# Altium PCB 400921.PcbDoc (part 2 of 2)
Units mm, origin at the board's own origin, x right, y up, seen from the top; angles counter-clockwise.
Board outline 33 x 32.99 mm, 4 copper layers (Top Layer, Mid-Layer 1, Mid-Layer 2, Bottom Layer), stack 0.75 mm thick; 113 components, 68 nets, 329 pads, 369 vias.
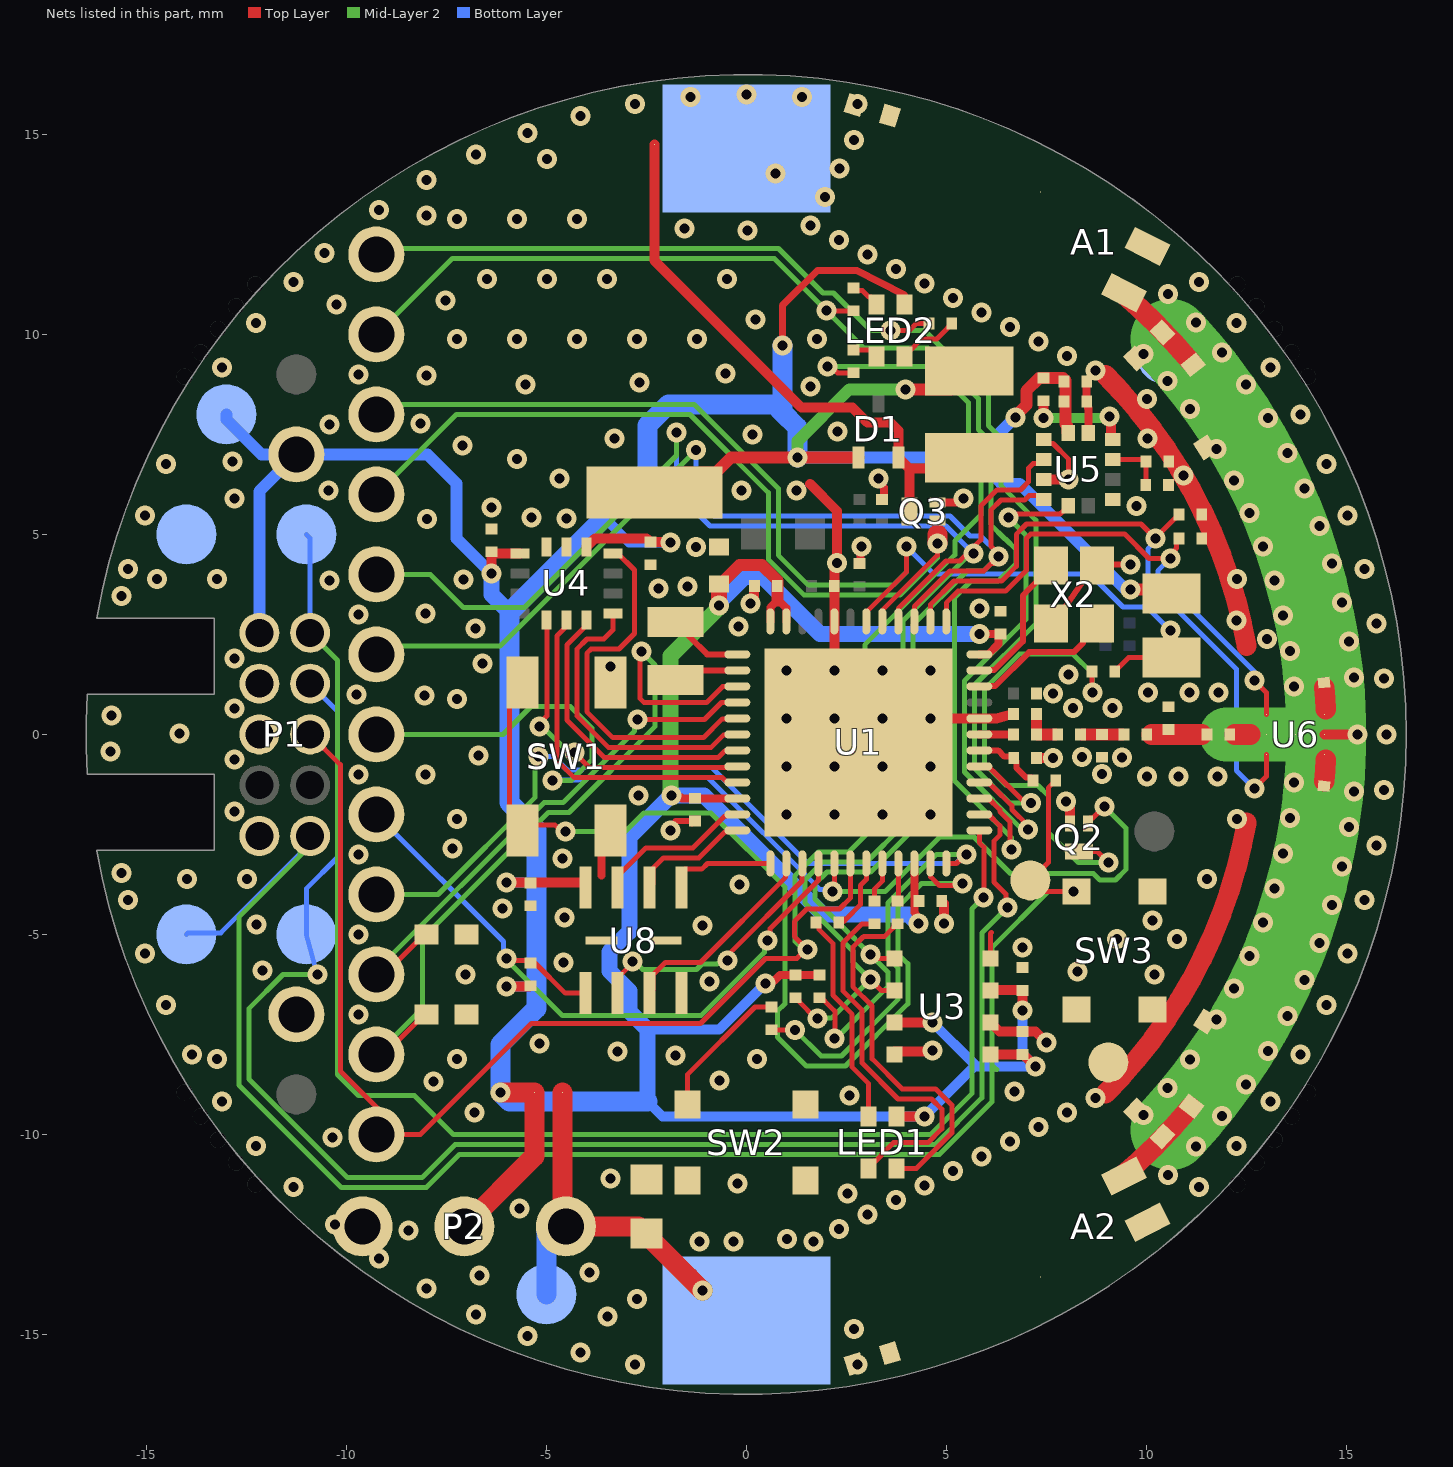
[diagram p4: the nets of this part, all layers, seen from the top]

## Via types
v1: diameter 0.5, hole 0.25, Top Layer to Bottom Layer, tented both sides, 369 vias

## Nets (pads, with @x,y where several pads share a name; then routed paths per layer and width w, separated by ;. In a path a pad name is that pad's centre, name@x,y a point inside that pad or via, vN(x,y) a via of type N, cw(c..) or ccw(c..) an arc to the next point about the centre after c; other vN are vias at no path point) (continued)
GND: A1.2 A2.2 Bat1.2 C1.1 C2.1 C3.1 C4.2 C5.1 C6.1 C7.2 C8.2 C9.1 C10.2 C11.1 C12.1 C13.1 C15.1 C16.1 C17.2 C18.1 C19.2 C20.1 C21.1 C22.1 C23.1 C24.1 C26.1 C27.1 C30.1 C31.1 C38.2 C39.1 C41.1 C42.1 GND.1 P1.3 P1.5 P1.9 P2.3 Q2.2 Q3.2 R8.1 R9.1 SW1.1 SW2.2 SW3.1 TP2.1 TP7.1 TP13.1 U1.32 U1.44 U1.49 U3.1 U3.5 U3.7 U4.6 U4.7 U5.1 U5.3 U5.7 U5.11 U6.5 U6.7 U8.4 U8.9 X2.2 X2.4 | length 63
  Top Layer w0.125: U3.5@6.1,-5.6 6.1,-4.975 6.125,-4.95 ; U5.1@7.44,7.375 7.542,7.273 7.668,7.273 8.05,6.89 v1(8.05,6.375)
  Top Layer w0.15: v1@-1.85,-2.25 -1.766,-2.166 C7.2@-1.287,-2.166 -1.302,-2.166 C7.2@-1.362,-2.226 ; X2.4@7.612,2.779 7.962,3.179 8.412,3.829 X2.2@8.762,4.229 ; X2.2@8.762,4.204 8.808,4.25 v1(9.6,4.25)
  Top Layer w0.2: -3.625,-3.525 -3.625,-2.625 SW1.1@-3.4,-2.4 ; C12.1@2.828,4.272 2.853,4.297 2.853,4.673 v1(2.879,4.698) ; v1(3.3,6.4) 3.3,6.319 3.44,6.179 C2.1@3.44,5.907 ; Q3.2@4.775,5.8 v1@5.425,5.8 ; C22.1@8.51,8.825 C21.1@8.51,8.325 8.545,8.29 8.545,8.163 8.55,8.158 U5.11@8.55,7.535 8.55,8.135
  Top Layer w0.25: v1(0.11,3.276) 0.11,3.343 0.196,3.429 0.196,3.697 C10.2@0.206,3.707 ; 1.59,6.265 2.269,5.587 2.269,4.224 2.21,4.165 2.21,3.719 C1.1@2.2,3.709 U1.44@2.2,2.825 v1(2.2,1.6) ; U3.1@3.7,-7.925 v1@4.65,-7.925 ; U1.49@4.603,0.4 U1.32@5.825,0.4 6.254,0.4 C6.1@6.681,0.514 ; C8.2@4.889,-4.162 4.889,-4.177 4.937,-4.225 v1(4.937,-4.725) ; U3.7@6.1,-7.2 6.33,-7.43 C16.1@6.9,-7.43 7.23,-7.43 v1(7.5,-7.7) ; C13.1@7.258,-0.586 v1@7.661,-0.586 ; U5.3@7.44,6.375 v1(8.05,6.375) ; Q2.2@8.087,-2.225 v1@8.087,-1.739 ; U6.5@14.45,0 v1(15.275,0)
  Top Layer w0.5: 8.98,-8.98 ccw(c0,0) 12.507,-2.205 ; 8.98,8.98 cw(c0,0) 12.507,2.205
  Mid-Layer 2 w1.35: 12.001,0 14.5,0
  Mid-Layer 2 w2: 10.605,-9.889 ccw(c0,0) 10.605,9.889
  other v1: -2.778,-15.757 2.778,-15.757 -4.141,-15.455 -5.472,-15.035 2.689,-14.863 -3.475,-14.55 -6.762,-14.501 -2.732,-14.118 -8,-13.856 -6.675,-13.525 -3.925,-13.45 -9.177,-13.106 -1.175,-12.675 -0.325,-12.675 1.675,-12.675 1.018,-12.618 -8.45,-12.4 2.313,-12.362 -10.285,-12.257 3.026,-11.999 -5.675,-11.85 3.738,-11.635 2.525,-11.475 -11.314,-11.314 11.314,-11.314 4.451,-11.272 -0.225,-11.225 -3.4,-11.1 10.546,-11.016 5.164,-10.909 5.877,-10.546 11.243,-10.303 -12.257,-10.285 12.257,-10.285 6.59,-10.183 -10.35,-10.075 7.303,-9.82 11.893,-9.545 9.932,-9.508 -6.8,-9.45 8.015,-9.456 -13.106,-9.177 13.106,-9.177 8.728,-9.093 2.575,-9.025 6.7,-8.925 10.533,-8.838 12.492,-8.747 -7.825,-8.675 -0.675,-8.65 11.089,-8.13 -13.232,-8.118 -7.232,-8.118 0.268,-8.118 -1.775,-8.025 -13.856,-8 13.856,-8 -3.225,-7.925 4.65,-7.9 13.037,-7.911 -5.175,-7.725 11.755,-7.133 13.527,-7.042 -9.7,-7 -14.501,-6.762 14.501,-6.762 12.196,-6.349 -0.925,-6.175 13.958,-6.142 -7.025,-6 10.2,-6 8.275,-5.925 -12.1,-5.9 -4.575,-5.7 12.586,-5.538 -15.035,-5.472 15.035,-5.472 6.9,-5.325 14.33,-5.216 9.268,-5.118 10.768,-5.118 -9.7,-5 -1.1,-4.775 -12.25,-4.75 12.921,-4.703 10.15,-4.65 -4.55,-4.575 -6.1,-4.35 14.641,-4.267 -15.455,-4.141 15.455,-4.141 13.201,-3.848 -0.175,-3.75 -13.982,-3.618 -12.482,-3.618 11.518,-3.618 -15.621,-3.463 14.888,-3.301 -4.6,-3.1 -9.7,-3 13.424,-2.976 -7.35,-2.85 15.757,-2.778 -1.9,-2.4 15.072,-2.32 -7.232,-2.118 12.268,-2.118 13.59,-2.092 1,-2 2.2,-2 3.4,-2 4.6,-2 -12.8,-1.925 7.988,-1.676 -2.7,-1.525 15.192,-1.429 15.939,-1.394 13.698,-1.198 10.016,-1.05 10.803,-1.05 11.775,-1.05 -9.7,-1 -8.025,-1 8.898,-0.989 1,-0.8 2.2,-0.8 3.4,-0.8 4.6,-0.8 -12.8,-0.625 7.666,-0.591 8.391,-0.56 9.394,-0.571 -6.7,-0.525 -15.9,-0.425 16,0 -14.175,0.025 1,0.4 2.2,0.4 3.4,0.4 4.6,0.4 -15.875,0.475 -12.8,0.65 8.162,0.659 9.152,0.659 -7.232,0.882 -8.05,0.975 -9.75,1 7.666,1.02 10.041,1.05 11.075,1.05 11.8,1.05 13.698,1.198 15.939,1.394 15.192,1.429 8.06,1.498 1,1.6 3.4,1.6 4.6,1.6 -3.4,1.7 -6.6,1.775 -12.8,1.9 13.59,2.092 15.072,2.32 13.018,2.382 -6.775,2.65 -0.2,2.702 15.757,2.778 12.25,2.85 13.424,2.976 -9.7,3 -8.025,3.025 5.825,3.149 14.888,3.301 -15.621,3.463 -2.2,3.65 -1.475,3.7 -10.425,3.85 13.201,3.848 -14.732,3.882 -13.232,3.882 -7.075,3.875 12.268,3.882 -15.455,4.141 15.455,4.141 14.641,4.267 2.269,4.292 -1.263,4.685 12.921,4.703 14.33,5.216 -7.982,5.382 -4.5,5.4 -5.375,5.425 -15.035,5.472 15.035,5.472 12.586,5.538 -6.375,5.675 9.75,5.707 -12.8,5.9 5.425,5.9 -10.45,6.1 -0.125,6.1 1.25,6.1 13.958,6.142 12.196,6.349 -4.675,6.4 10.926,6.474 -14.501,6.762 14.501,6.762 -12.85,6.825 -5.732,6.882 13.527,7.042 11.755,7.133 -7.1,7.225 -3.3,7.4 10.025,7.4 0.15,7.5 2.275,7.575 -10.425,7.75 -8.15,7.775 13.037,7.911 13.856,8 11.089,8.13 10.018,8.382 1.6,8.7 -5.525,8.75 12.492,8.747 -2.675,8.8 10.533,8.838 -8,8.975 -9.7,9 -0.525,9.025 8.728,9.093 -13.106,9.177 -13.106,9.177 13.106,9.177 8.015,9.456 9.932,9.508 11.893,9.545 7.303,9.82 -7.232,9.882 -5.732,9.882 -4.232,9.882 -2.732,9.882 -1.232,9.882 1.768,9.882 6.59,10.183 -12.257,10.285 -12.257,10.285 12.257,10.285 11.243,10.303 0.225,10.375 5.877,10.546 -10.25,10.75 -7.525,10.85 5.164,10.909 10.546,11.016 4.451,11.272 -11.314,11.314 11.314,11.314 -6.482,11.382 -4.982,11.382 -3.482,11.382 -0.482,11.382 3.738,11.635 3.026,11.999 -10.55,12.029 2.313,12.362 0.025,12.6 -1.55,12.65 1.6,12.725 -7.232,12.882 -5.732,12.882 -4.232,12.882 -8,12.975 -9.177,13.106 1.963,13.438 -8,13.856 0.725,14.025 2.326,14.151 -4.982,14.382 -6.762,14.501 2.69,14.863 -5.472,15.035 -4.141,15.455 -2.778,15.757 2.778,15.757 -1.394,15.939 1.394,15.939 0,16
J1: C29.2 U6.6 | length 0.5
  Top Layer w0.517: C29.2@14.453,1.171 cw(c0,0) 14.486,0.634
J2: C25.2 U6.4 | length 0.5
  Top Layer w0.517: C25.2@14.453,-1.171 ccw(c0,0) 14.486,-0.634
NetA1_1: A1.1 C31.2 L7.2 | length 2.5
  Top Layer w0.517: A1.1@9.34,11.091 cw(c0,0) L7.2@11.102,9.327
NetA1_3: A1.3 C42.2
NetA2_1: A2.1 C27.2 C40.2 | length 2.5
  Top Layer w0.517: A2.1@9.34,-11.091 ccw(c0,0) C40.2@11.102,-9.327
NetA2_3: A2.3 C41.2
NetBz1_2: Bz1.2 D1.2 L6.1 Q3.3 | length 14.5
  Top Layer w0.25: Bz1.2@-2.3,14.75 -2.3,11.85 1.375,8.175 2.65,8.175 3.025,7.8 3.6,7.8 3.8,7.6 D1.2@3.8,6.925 4.075,6.65 ; Q3.3@4.075,5.575 4.075,6.65 ; L6.1@5.575,6.915 5.31,6.65 4.075,6.65
NetC6_2: C6.2 L2.2 L3.1 | length 0.9
  Top Layer w0.27: L2.2@7.253,0.014 C6.2@7.253,0.507
  Top Layer w0.3: L2.2@7.28,-0.001 L3.1@7.73,-0.001
NetC9_2: C9.2 L3.2 L4.1 | length 1
  Top Layer w0.3: L3.2@8.391,-0.001 C9.2@8.898,-0.001 L4.1@9.406,-0.001
NetC13_2: C13.2 R1.1 U1.30 | length 1.7
  Top Layer w0.15: U1.30@5.825,-0.4 6.297,-0.4 6.452,-0.555 6.635,-0.555 C13.2@6.685,-0.605 ; C13.2@6.684,-0.613 6.7,-0.613 6.755,-0.669 6.755,-0.74 6.757,-0.742 6.757,-0.843 6.996,-1.082 R1.1@7.136,-1.082
NetL2_1: L2.1 U1.31 | length 0.9
  Top Layer w0.2: U1.31@5.825,0 6.682,0 L2.1@6.683,-0.001
NetLED1_1: LED1.1 R13.2 | length 5.4
  Top Layer w0.125: R13.2@1.74,-4.7 1.812,-4.772 1.812,-4.871 2.162,-5.221 2.162,-6.513 2.646,-6.997 2.646,-8.318 3.05,-8.722 LED1.1@3.05,-9.55
NetLED1_2: LED1.2 R12.2 | length 9.3
  Top Layer w0.125: LED1.2@3.75,-10.85 4.25,-10.85 5.138,-9.962 5.138,-9.265 4.735,-8.862 3.897,-8.862 3.146,-8.111 3.146,-6.79 2.662,-6.306 2.662,-5.944 2.662,-5.319 2.919,-5.062 2.935,-5.062 2.94,-5.058 3.453,-5.058 3.688,-4.822 3.688,-4.807 3.76,-4.735 R12.2@3.775,-4.735
NetLED1_3: LED1.3 R11.2 | length 9.4
  Top Layer w0.125: LED1.3@3.05,-10.85 3.05,-10.8 3.187,-10.662 3.238,-10.662 3.362,-10.538 3.362,-10.522 3.685,-10.2 4.546,-10.2 4.887,-9.859 4.887,-9.369 4.631,-9.113 3.794,-9.113 2.896,-8.215 2.896,-6.893 2.412,-6.41 2.412,-5.215 2.893,-4.735 R11.2@3.2,-4.735
NetLED2_1: LED2.1 R16.2 | length 0.8
  Top Layer w0.125: R16.2@2.675,11.16 2.743,11.092 2.908,11.092 3.063,10.937 3.113,10.937 3.25,10.8 LED2.1@3.25,10.75
NetLED2_2: LED2.2 R15.2 | length 1.8
  Top Layer w0.125: LED2.2@3.95,9.45 3.95,9.5 4.088,9.637 4.138,9.637 4.215,9.715 ; 4.215,9.715 4.387,9.888 4.68,9.888 ; 4.748,9.888 4.68,9.888 ; R15.2@5.048,10.188 5.063,10.188 R15.2@5.135,10.26 ; R15.2@5.135,10.275 R15.2@5.135,10.26 ; 4.68,9.888 4.763,9.888 R15.2@5.135,10.26
NetLED2_3: LED2.3 R14.2 | length 0.8
  Top Layer w0.125: R14.2@2.675,9.61 3.113,9.61 3.25,9.473 LED2.3@3.25,9.45 LED2.3@3.365,9.335
NetQ2_3: Q2.3 R4.1 | length 11.6
  Top Layer w0.125: Q2.3@8.3,-2.925 8.775,-2.925 v1(9.05,-3.2) ; R4.1@8.64,1.575 8.64,1.06 v1(8.65,1.05)
  Mid-Layer 2 w0.125: v1(8.65,1.05) 8.65,1.527 8.165,2.011 6.836,2.011 5.957,1.132 5.957,-0.734 6.5,-1.277 7.294,-1.277 7.55,-1.533 7.55,-2.45 8.3,-3.2 v1(9.05,-3.2)
NetR5_2: R5.2 U5.10 | length 2.7
  Top Layer w0.25: v1(7.425,7.915) R5.2@7.425,8.34 ; v1(9.075,7.95) 9.121,7.904 9.121,7.414 U5.10@9.16,7.375
  Mid-Layer 2 w0.25: v1(7.425,7.915) 9.04,7.915 v1(9.075,7.95)
NetR19_1: R19.1 SW2.1 | length 3.5
  Top Layer w0.125: SW2.1@-1.475,-9.25 -1.475,-8.506 0.216,-6.815 R19.1@0.625,-6.815
P0.00: SW1.2 U1.23 | length 25.3
  Top Layer w0.125: SW1.2@-5.6,1.3 -5.925,0.975 -5.925,-2.075 SW1.2@-5.6,-2.4 -5.461,-2.261 -4.786,-2.261 -4.621,-2.425 v1(-4.525,-2.425) ; U1.23@4.609,-3.234 4.609,-3.559 4.827,-3.777 5.348,-3.777 v1(5.4,-3.725)
  Mid-Layer 2 w0.125: v1(-4.525,-2.425) -3.025,-2.425 -2.562,-1.962 -0.886,-1.962 0.962,-3.811 0.962,-6.738 0.778,-6.922 0.778,-7.566 1.502,-8.291 2.482,-8.291 4.037,-6.735 4.037,-5.73 3.788,-5.48 3.788,-4.318 4.38,-3.725 v1(5.4,-3.725)
P0.01: 0.01.1 R19.2 U1.24 | length 27.6
  Top Layer w0.125: R19.2@0.625,-7.385 v1(1.216,-7.385) ; U1.24@5,-3.225 5.254,-3.225 5.479,-3 v1(5.5,-3)
  Mid-Layer 2 w0.125: 0.01.1@-9.25,-4 -7.707,-4 -5.288,-1.58 -5.288,-0.638 v1(-5.2,-0.55) ; v1(1.216,-7.385) 1.871,-8.041 2.3,-8.041 2.303,-8.038 2.381,-8.038 3.787,-6.631 3.787,-5.834 3.537,-5.584 3.537,-4.214 4.752,-3 v1(5.5,-3)
  Bottom Layer w0.125: v1(-5.2,-0.55) -4.819,-0.55 -4.481,-0.888 -4.119,-0.888 -4.062,-0.831 -0.856,-0.831 1.538,-3.225 5.239,-3.225 5.464,-3 v1(5.5,-3)
P0.02: 0.02.1 R16.1 U1.27 | length 33
  Top Layer w0.125: v1@2,10.59 R16.1@2.675,10.59 ; U1.27@5.825,-1.6 6.057,-1.6 6.337,-1.881 6.337,-1.927 6.587,-2.177 6.587,-2.838 v1(6.625,-2.875)
  Mid-Layer 2 w0.125: 0.02.1@-9.25,10 -7.35,11.9 0.7,11.9 v1(2,10.6) 2.938,9.662 4.538,9.662 5.8,8.4 5.8,7.621 6.113,7.309 6.113,5.244 6.469,4.888 6.481,4.888 6.737,4.631 6.737,4.269 6.306,3.837 5.62,3.837 5.207,3.425 5.207,-1.157 6.625,-2.575 v1(6.625,-2.875)
P0.03: U1.28 U5.5 | length 12.8
  Top Layer w0.125: U1.28@5.835,-1.21 U1.28@5.825,-1.2 6.048,-1.2 6.161,-1.312 6.169,-1.312 6.639,-1.782 6.639,-1.875 7.037,-2.274 v1(7.037,-2.381) ; v1(6.55,5.425) 6.634,5.509 7.844,5.509 7.917,5.583 7.947,5.583 8.05,5.685 U5.5@8.05,5.715
  Mid-Layer 2 w0.125: v1(6.55,5.425) 6.988,4.988 6.988,2.87 5.457,1.339 5.457,-0.941 6.897,-2.381 v1(7.037,-2.381)
P0.04: 0.04.1 R15.1 U1.29 | length 32.1
  Top Layer w0.125: v1(3.6,10.1) 4.075,10.1 4.25,10.275 R15.1@4.565,10.275 ; U1.29@5.825,-0.8 6.05,-0.8 6.162,-0.912 6.169,-0.912 6.933,-1.676 7.226,-1.676 v1@7.264,-1.714
  Mid-Layer 2 w0.125: 0.04.1@-9.25,12 -9.1,12.15 0.804,12.15 1.916,11.038 2.181,11.038 3.119,10.1 v1(3.6,10.1) 4.454,10.1 6.05,8.504 6.05,7.725 6.363,7.412 6.363,6.231 7.238,5.356 7.238,2.766 5.707,1.235 5.707,-0.837 6.584,-1.714 v1@7.287,-1.714
  other v1: 7.112,-1.714
P1.00/XL1: U1.1 X1.2 | length 2.1
  Top Layer w0.15: X1.2@-1.998,2.781 -1.749,2.781 -1.399,2.431 -1.399,2.422 -0.977,2 U1.1@-0.225,2
P1.01/XL2: U1.2 X1.1 | length 1.9
  Top Layer w0.15: X1.1@-2.024,1.281 -1.699,1.281 -1.379,1.6 U1.2@-0.225,1.6
P1.02/NFC1: 1.02.1 C17.1 U1.3 | length 18.9
  Top Layer w0.125: 1.02.1@-9.25,-8 -9.05,-8 -8.05,-7 C17.1@-8,-7 ; v1@-2.674,2.051 v1@-2.65,2.075 ; v1@-2.661,2.039 -2.661,0.903 -2.551,0.793 -0.996,0.793 -0.589,1.2 U1.3@-0.225,1.2
  Mid-Layer 2 w0.125: 1.02.1@-9.25,-8 -8.1,-6.85 -8.1,-5.1 -4.95,-1.95 -4.431,-1.95 -2.287,0.194 -2.287,0.622 -2.284,0.625 -2.284,1.734 v1(-2.625,2.075)
P1.03/NFC2: 1.03.1 C19.1 U1.4 | length 13.7
  Top Layer w0.125: 1.03.1@-9.25,-6 -9.05,-6 -8.05,-5 C19.1@-8,-5 ; v1(-2.725,0.375) -1.045,0.375 -0.62,0.8 U1.4@-0.225,0.8
  Mid-Layer 2 w0.125: 1.03.1@-9.25,-6 -9.25,-5.896 -5.054,-1.7 -4.578,-1.7 -2.797,0.081 -2.797,0.303 v1(-2.725,0.375)
P1.04: U1.5 U4.4 | length 9.4
  Top Layer w0.125: U4.4@-3.338,4.525 -3.21,4.525 -2.794,4.109 -2.794,2.525 -3.181,2.138 -3.878,2.138 -3.988,2.028 -3.988,0.57 -3.337,-0.081 -1.069,-0.081 -0.597,0.391 U1.5@-0.234,0.391
P1.05: U1.6 U4.1 | length 7.6
  Top Layer w0.125: U4.1@-3.337,3 -3.337,2.613 -3.562,2.388 -3.981,2.388 -4.238,2.131 -4.238,0.466 -3.44,-0.331 -0.887,-0.331 -0.565,-0.009 U1.6@-0.234,-0.009
P1.06: U1.7 U4.14 | length 7.4
  Top Layer w0.125: U4.14@-4,2.813 -4,2.722 -4.488,2.235 -4.488,0.363 -3.544,-0.581 -0.705,-0.581 -0.533,-0.409 U1.7@-0.234,-0.409
P1.07: U1.8 U4.12 | length 8.1
  Top Layer w0.125: v1(-5.175,0.2) -5.175,0.273 -4.988,0.461 U4.12@-4.988,2.825 ; v1(-4.3,-0.45) -3.919,-0.831 -0.256,-0.831 U1.8@-0.225,-0.8
  Mid-Layer 2 w0.125: v1(-5.175,0.2) -5.1,0.2 -4.522,-0.378 -4.372,-0.378 v1(-4.3,-0.45)
P1.08: U1.9 U4.13 | length 8.3
  Top Layer w0.125: U4.13@-4.5,2.863 -4.5,2.7 -4.738,2.462 -4.738,-0.644 -4.3,-1.081 -0.594,-1.081 -0.475,-1.2 U1.9@-0.225,-1.2
P1.09: R8.2 U1.37 U6.1 | length 13.2
  Top Layer w0.125: U1.37@5,2.825 5,3.289 5.298,3.587 6.486,3.587 7,4.1 7,4.9 7.108,5.009 9.46,5.009 10.069,4.4 v1(10.6,4.4) 10.6,4.501 10.754,4.656 10.754,4.839 R8.2@10.815,4.9 ; v1(12.7,1.35) 13,1.05 U6.1@13,0.5
  Bottom Layer w0.125: v1(10.6,4.4) 10.289,4.089 10.289,3.986 12.7,1.575 v1(12.7,1.35)
P1.10: R9.2 U1.38 U6.3 | length 16.8
  Top Layer w0.125: U1.38@4.6,2.825 4.6,3.242 5.194,3.837 6.383,3.837 6.75,4.203 6.75,5.003 7.005,5.259 9.866,5.259 v1(10.225,4.9) 10.225,4.91 10.728,5.413 10.743,5.413 10.815,5.485 R9.2@10.815,5.5 ; v1(12.7,-1.35) 13,-1.05 U6.3@13,-0.5
  Bottom Layer w0.125: v1(10.225,4.9) 10.225,4.827 10.038,4.639 10.038,3.847 12.25,1.634 12.25,-0.9 v1(12.7,-1.35)
P1.11: 1.11.1 R3.1 U1.39 U3.4 U5.4 | length 43.7
  Top Layer w0.125: R3.1@1.825,-6.585 1.898,-6.658 1.951,-6.658 2.213,-6.919 v1@2.213,-7.587 ; v1@3.1,-5.6 v1@3.301,-5.6 ; v1(3.1,-5.5) 3.201,-5.5 v1@3.301,-5.6 ; U3.4@3.7,-5.6 v1@3.301,-5.6 ; U1.39@4.2,2.825 4.2,3.196 5.091,4.087 5.939,4.087 6.128,4.275 6.2,4.275 6.2,4.376 v1@6.287,4.463 ; v1(6.3,4.45) 6.3,4.523 6.113,4.711 6.113,5.606 6.369,5.863 6.958,5.863 7.07,5.975 7.315,5.975 7.428,5.863 U5.4@7.44,5.875
  Mid-Layer 2 w0.125: 1.11.1@-9.25,2 -9.25,2.213 -6.154,2.213 v1(-1.258,7.108) ; v1(2.2,-7.6) 2.244,-7.6 3.537,-6.306 3.537,-5.937 v1(3.1,-5.5) 2.8,-5.2 2.8,-5.196 2.654,-5.05 2.65,-5.05 1.712,-4.112 1.712,-3.744 2.017,-3.44 3.11,-3.44 4.162,-2.388 4.162,2.734 5.516,4.087 5.937,4.087 v1(6.3,4.45)
  Bottom Layer w0.125: v1(-1.258,7.108) -1.258,5.912 -0.805,5.459 5.095,5.459 5.591,4.962 5.856,4.962 6.3,4.519 v1(6.3,4.45)
P1.12: 1.12.1 R2.1 U1.40 U3.3 U5.2 | length 42.7
  Top Layer w0.125: R2.1@1.225,-6.585 1.24,-6.585 1.312,-6.658 1.312,-6.673 v1@1.74,-7.1 ; v1@1.763,-7.112 v1(1.775,-7.1) ; v1(3.1,-6.125) 3.375,-6.4 U3.3@3.7,-6.4 ; U1.40@3.8,2.825 3.8,3.149 4.987,4.337 5.333,4.337 5.45,4.453 5.502,4.453 5.598,4.55 5.598,4.602 5.863,4.866 5.863,5.71 6.265,6.113 6.854,6.113 7.057,6.316 7.057,6.657 7.173,6.773 7.337,6.773 U5.2@7.44,6.875
  Mid-Layer 2 w0.125: 1.12.1@-9.25,4 -7.9,4 -7.075,3.175 -5.545,3.175 -1.746,6.974 v1(-1.746,7.546) ; v1(1.775,-7.1) 1.784,-7.091 2.134,-7.091 v1(3.1,-6.125) 2.662,-5.687 2.662,-5.416 1.462,-4.216 1.462,-3.638 1.91,-3.19 3.007,-3.19 3.912,-2.284 3.912,2.837 5.6,4.525 v1(5.675,4.525)
  Bottom Layer w0.125: v1(-1.746,7.546) -1.746,6.046 -0.909,5.209 4.991,5.209 v1(5.675,4.525)
P1.13: 1.13.1 Q3.1 U1.41 | length 21.2
  Top Layer w0.125: U1.41@3.4,2.825 3.4,3.103 4.775,4.478 v1(4.775,4.771)
  Top Layer w0.5: v1(4.775,4.771) v1@4.775,5
  Mid-Layer 2 w0.125: 1.13.1@-9.25,6 -7.25,8 -1.406,8 0.55,6.044 0.55,4.378 1.447,3.481 3.849,3.481 4.775,4.407 v1(4.775,4.771)
P1.14: 1.14.1 Q1.E R4.2 U1.42 | length 28.3
  Top Layer w0.125: U1.42@3,2.825 3,3.057 4,4.057 v1(4,4.7) ; R4.2@9.21,1.575 9.21,1.59 9.282,1.663 9.297,1.663 9.56,1.925 Q1.E@10.625,1.925
  Mid-Layer 2 w0.125: 1.14.1@-9.25,8 -9,8.25 -1.303,8.25 0.8,6.147 0.8,4.481 1.551,3.731 3.669,3.731 4,4.061 v1(4,4.7)
  Bottom Layer w0.125: v1(4,4.7) 4.687,4.013 8.594,4.013 9.419,3.188 10.012,3.188 v1(10.6,2.6)
P2.00: U1.11 U8.7 | length 4.2
  Top Layer w0.125: U8.7@-3.275,-4.054 -3.275,-3.6 -2.513,-2.838 -1.338,-2.838 -0.537,-2.037 -0.508,-2.037 -0.47,-2 U1.11@-0.225,-2
P2.01: U1.12 U8.6 | length 3
  Top Layer w0.125: U8.6@-2.425,-3.83 -2.337,-3.743 -2.337,-3.352 -2.073,-3.088 -1.188,-3.088 -0.537,-2.437 -0.508,-2.437 -0.47,-2.4 U1.12@-0.225,-2.4
P2.02: U1.13 U8.5 | length 2.7
  Top Layer w0.125: U8.5@-1.625,-3.83 -1.625,-3.457 -1.537,-3.37 -1.116,-3.37 -0.971,-3.225 U1.13@0.6,-3.225
P2.03: U1.14 U8.3 | length 5.5
  Top Layer w0.125: U8.3@-2.425,-6.47 -2.337,-6.383 -2.337,-6.008 -2.333,-6.008 -2.025,-5.7 -1.146,-5.7 0.986,-3.569 0.986,-3.239 U1.14@1,-3.225 U1.14@1,-3.508
P2.04: U1.15 U8.2 | length 6.7
  Top Layer w0.125: U8.2@-3.225,-6.47 -3.225,-6.095 -2.85,-5.72 v1(-2.85,-5.675) ; v1(-0.475,-5.65) -0.403,-5.578 -0.403,-5.46 1.394,-3.663 1.394,-3.231 U1.15@1.4,-3.225
  Mid-Layer 2 w0.125: v1(-2.85,-5.675) -2.789,-5.675 -2.589,-5.875 -1.244,-5.875 -1.106,-5.737 -0.736,-5.737 -0.72,-5.722 -0.547,-5.722 v1(-0.475,-5.65)
P2.05: 2.05.1 R17.1 U1.16 U8.1 | length 17.8
  Top Layer w0.125: v1(-6,-5.6) -5.943,-5.657 -5.458,-5.657 R17.1@-5.4,-5.715 -5.28,-5.715 -4.525,-6.47 U8.1@-4.025,-6.47 ; v1(0.525,-5.15) 0.597,-5.078 0.597,-4.853 1.8,-3.65 U1.16@1.8,-3.225
  Mid-Layer 2 w0.125: v1(-6,-5.6) -6,-5.625 -4.6,-7.025 -1.125,-7.025 0.453,-5.447 0.453,-5.222 v1(0.525,-5.15)
  Bottom Layer w0.125: 2.05.1@-9.25,-2 -6.072,-5.178 -6.072,-5.528 v1(-6,-5.6)
P2.06: 2.06.1 Q2.1 U1.17 | length 27.7
  Top Layer w0.125: v1(2.15,-3.925) 2.2,-3.875 U1.17@2.2,-3.225 ; Q2.1@8.525,-2.225 8.525,-2.15 8.588,-2.088 8.662,-2.088 v1(8.95,-1.8)
  Mid-Layer 2 w0.125: 2.06.1@-9.25,0 -6.083,0 -5.383,0.7 -4.4,0.7 -3.862,0.162 -3.862,-0.631 -4.381,-1.15 v1(-4.85,-1.15) ; v1(2.15,-3.925) 3.473,-3.925 4.836,-2.562 5.694,-2.562 6.606,-3.475 8.675,-3.475 8.838,-3.638 9.231,-3.638 9.488,-3.381 9.488,-2.338 v1(8.95,-1.8)
  Bottom Layer w0.125: v1(-4.85,-1.15) -4.838,-1.138 -4.015,-1.138 -3.959,-1.081 -0.959,-1.081 1.833,-3.873 2.098,-3.873 v1(2.15,-3.925)
P2.07: 2.07.1 P1.6 R14.1 U1.18 | length 47.7
  Top Layer w0.125: P1.6@-10.905,0 -10.15,-0.755 -10.15,-8.414 -9.25,-9.314 2.07.1@-9.25,-10 -8.15,-10 -5.375,-7.225 -1.144,-7.225 0.481,-5.6 1.264,-5.6 1.489,-5.375 v1(1.525,-5.375) 1.2,-5.05 1.2,-4.675 1.512,-4.363 2.331,-4.363 2.6,-4.094 U1.18@2.6,-3.225 ; v1(2.025,9.2) 2.126,9.2 2.286,9.04 R14.1@2.675,9.04
  Mid-Layer 2 w0.125: v1(1.525,-5.375) 1.424,-5.375 1.294,-5.246 1.286,-5.246 1.212,-5.172 1.212,-3.534 1.807,-2.94 2.56,-2.94 2.962,-2.538 2.962,2.241 5.213,4.491 5.213,4.838 5.863,5.487 5.863,7.205 5.55,7.518 5.55,8.296 4.646,9.2 v1(2.025,9.2)
P2.08: R13.1 U1.19 | length 2
  Top Layer w0.125: R13.1@2.31,-4.7 2.31,-4.685 2.382,-4.613 2.496,-4.613 ; R13.1@2.352,-4.757 2.496,-4.613 ; U1.19@3,-3.225 3,-3.625 2.85,-3.775 2.85,-4.258 2.496,-4.613
P2.09: R11.1 U1.20 | length 1
  Top Layer w0.125: R11.1@3.2,-4.165 3.2,-3.868 3.4,-3.668 U1.20@3.4,-3.225
P2.10: R12.1 U1.21 | length 0.9
  Top Layer w0.125: R12.1@3.8,-4.14 U1.21@3.8,-3.225
RESET: P1.10 R1.2 SW3.2 TP3.1 TP12.1 | length 43.4
  Top Layer w0.125: R1.2@7.736,-1.152 7.55,-1.337 7.55,-3.2 TP12.1@7.1,-3.65 7.375,-3.925 v1(8.175,-3.925)
  Mid-Layer 2 w0.125: 6.263,-8.382 6.137,-8.257 ; v1(8.175,-3.925) 7.544,-3.925 6.137,-5.331 6.137,-8.257 ; -11.163,-3.044 -10.905,-2.786 P1.10@-10.905,-2.54 -11.163,-2.798 -11.163,-3.044 ; -11.163,-3.044 -12.688,-4.569 -12.688,-8.762 -10.125,-11.325 -8,-11.325 -7.175,-10.5 4.826,-10.5 6.137,-9.188 6.137,-8.257
  Bottom Layer w0.125: TP3.1@-14,-5 -13.961,-4.961 -13.136,-4.961 P1.10@-10.905,-2.73 ; P1.10@-10.905,-2.73 P1.10@-10.905,-2.54 P1.10@-10.905,-2.73
RF: C11.2 C28.2 L4.2 | length 1.3
  Top Layer w0.517: L4.2@10.138,0 C28.2@11.39,0
RFC: C28.1 U6.2 | length 0.4
  Top Layer w0.517: C28.1@12.21,0 12.6,0
SWDCLK: P1.4 TP4.1 U1.26 | length 39.8
  Top Layer w0.125: U1.26@5.825,-2 6.057,-2 6.337,-2.281 6.337,-2.519 6.188,-2.669 6.188,-3.688 6.49,-3.991 6.49,-4.29 v1(6.525,-4.325)
  Mid-Layer 2 w0.125: v1(-10.725,-6) -11.581,-6 -12.438,-6.856 -12.438,-8.612 -9.975,-11.075 -8.104,-11.075 -7.279,-10.25 4.722,-10.25 5.887,-9.085 5.887,-4.963 v1(6.525,-4.325)
  Bottom Layer w0.125: P1.4@-10.905,1.27 -10.217,0.582 -10.217,-3.075 -11,-3.858 TP4.1@-11,-5 v1(-10.725,-6)
SWDIO: P1.2 TP5.1 U1.25 | length 37.6
  Top Layer w0.125: U1.25@5.825,-2.4 5.825,-2.706 5.938,-2.819 5.938,-4.062 v1(5.925,-4.075)
  Mid-Layer 2 w0.125: P1.2@-10.905,2.54 -10.217,1.852 -10.217,-6.621 -10.217,-8.508 -9.7,-9.025 -8.3,-9.025 -7.325,-10 4.619,-10 5.637,-8.981 5.637,-4.363 v1(5.925,-4.075)
  Bottom Layer w0.125: P1.2@-10.905,2.54 TP5.1@-10.905,4.905 ; TP5.1@-10.905,4.905 TP5.1@-11,5 TP5.1@-10.905,4.905
VBAT: Bat1.1 C39.2 P2.1 SB1.1 TP6.1 | length 9.6
  Top Layer w0.5: SB1.1@-4.599,-8.955 -4.599,-12.211 P2.1@-4.51,-12.3 -2.7,-12.3 -1.438,-13.563 ; -1.775,-13.225 -1.438,-13.563 ; v1(-1.1,-13.9) -1.438,-13.563
  Bottom Layer w0.5: TP6.1@-5,-14 -4.992,-13.992 P2.1@-4.992,-12.3
VDD: Bz1.1 C3.2 C4.1 C7.1 C8.1 C10.1 C15.2 C16.2 C18.2 C20.2 C21.2 C22.2 C38.1 D1.1 L6.2 LED1.4 LED2.4 P1.1 P2.2 Q1.C R2.2 R3.2 R5.1 R17.2 SB1.2 TP1.1 U1.10 U1.22 U1.36 U1.47 U1.48 U3.2 U3.6 U3.8 U4.5 U4.8 U5.12 U8.8 VDD.1 | length 149.4
  Top Layer w0.125: U3.6@6.1,-6.4 U3.6@6.108,-6.392
  Top Layer w0.175: v1(0.9,9.725) 0.9,10.725 1.776,11.601 2.754,11.601 ; 2.754,11.601 LED2.4@3.95,10.992 ; LED2.4@3.95,10.75 LED2.4@3.951,10.991
  Top Layer w0.2: v1(-1.875,-1.525) -1.818,-1.582 -1.625,-1.582 -1.608,-1.6 U1.10@-0.225,-1.6 ; v1(0.475,-6.225) 0.532,-6.168 0.69,-6.168 0.842,-6.015 R2.2@1.225,-6.015 R3.2@1.825,-6.015 ; U1.48@0.6,2.825 0.6,3.176 0.776,3.352 0.791,3.368 1,3.159 U1.47@1,2.825 ; U1.22@4.2,-3.225 4.2,-4.458 4.244,-4.502 4.244,-4.668 v1(4.301,-4.725) ; U1.36@5.825,2 6.05,2 6.05,2.002 6.308,2.26 C4.1@6.308,2.448 ; v1(5.825,2.514) 5.834,2.505 6.321,2.505 C4.1@6.343,2.483
  Top Layer w0.25: v1(-6.375,4.025) C20.2@-6.375,4.565 ; C20.2@-6.3,4.525 U4.8@-5.663,4.525 ; v1(-6,-6.3) -5.415,-6.3 R17.2@-5.4,-6.285 ; v1(-6,-3.7) U8.8@-4.155,-3.7 ; U4.5@-4,4.688 -3.788,4.9 -2.49,4.9 C18.2@-2.4,4.81 -1.91,4.81 v1(-1.9,4.8) ; U3.2@3.7,-7.2 v1(4.65,-7.2) ; LED1.4@3.75,-9.55 v1(4.45,-9.55) ; U3.8@6.1,-8 6.5,-8 C16.2@6.9,-8 6.925,-8 v1(7.225,-8.3) ; U3.6@6.108,-6.392 6.893,-6.392 C15.2@6.9,-6.4 v1(6.9,-6.9)
  Top Layer w0.3: Bz1.1@-2.3,6.05 -1.8,6.55 -0.75,6.55 -0.375,6.925 v1(1.281,6.925) D1.1@2.8,6.925 ; C3.2@-0.677,3.723 -0.165,4.235 0.39,4.235 0.776,3.85 C10.1@0.776,3.707 0.776,3.352 ; v1(3.975,8.625) 5.115,8.625 L6.2@5.575,9.085 ; v1(6.725,7.925) 6.725,7.957 7,8.232 7,8.589 7.321,8.91 R5.1@7.425,8.91 7.915,8.91 7.975,8.85 7.975,7.756 8.035,7.696 8.035,7.55 U5.12@8.05,7.535 ; v1(9.6,3.625) Q1.C@10.6,3.625 ; Q1.C@10.6,3.5 Q1.C@10.625,3.525
  Top Layer w0.4: v1(-0.677,3.222) C3.2@-0.677,3.723
  Top Layer w0.5: P2.2@-7.05,-12.3 -5.299,-10.549 SB1.2@-5.299,-8.955 -5.304,-8.95 v1(-6.15,-8.95)
  Mid-Layer 2 w0.3: v1(1.281,6.925) 1.281,7.331 2.575,8.625 v1(3.975,8.625)
  Mid-Layer 2 w0.4: v1@-1.897,-1.525 -1.897,1.955 v1@-0.697,3.155
  Bottom Layer w0.25: v1(-6,-6.3) -5.289,-6.3 ; v1(-6,-3.7) -5.289,-3.7 ; -5.25,-3.106 -5.244,-3.1 ; -3.552,5.423 -2.93,4.8 v1(-1.9,4.8) ; -2.469,-9.175 -2.094,-9.55 v1(4.45,-9.55) 5.7,-8.3 ; -2.469,-7.381 -0.681,-7.381 v1(0.475,-6.225) ; v1(4.65,-7.2) 4.657,-7.2 5.7,-8.243 5.7,-8.3 ; v1(6.9,-6.9) 6.9,-7.975 v1(7.225,-8.3) 5.7,-8.3
  Bottom Layer w0.3: TP1.1@-13,8 -13,7.875 -12.125,7 VDD.1@-11.25,7 ; P1.1@-12.175,2.54 -12.175,6.075 VDD.1@-11.25,7 ; v1(-6.375,4.025) -7.25,4.9 -7.25,6.275 -7.975,7 VDD.1@-11.25,7 ; v1(1.281,6.925) 5.725,6.925 ; v1(6.725,7.925) 5.725,6.925 ; v1(9.6,3.625) 9.475,3.625 6.835,6.265 6.385,6.265 5.725,6.925
  Bottom Layer w0.4: v1(-6.375,4.025) -6.375,3.5 -5.925,3.05 ; -2.469,-9.175 -2.469,-7.381 -2.925,-6.925 -2.925,-6.413 -3.425,-5.913 -3.425,-5.437 -2.925,-4.937 -2.925,-2.575 v1(-1.875,-1.525) -1.063,-1.525 1.912,-4.5 4.049,-4.5 4.274,-4.725 v1(4.301,-4.725) ; v1(-0.677,3.222) -0.677,3.301 -0.043,3.936 0.415,3.936 1.837,2.514 v1(5.825,2.514)
  Bottom Layer w0.5: -5.244,-2.381 -5.25,-2.375 ; -2.469,-9.175 -5.925,-9.175 v1(-6.15,-8.95) -6.15,-7.75 -5.25,-6.85 -5.25,-3.106 -5.25,-2.375 ; v1(0.9,9.725) 0.9,8.056 ; v1(1.281,6.925) 1.281,7.675 0.9,8.056 ; -5.25,-2.375 -5.585,-2.04 -5.925,-1.7 -5.925,3.05 -3.552,5.423 -2.475,6.5 -2.475,7.725 -1.95,8.25 0.706,8.25 0.9,8.056
VREG: C23.2 C24.2 U5.9 | length 1.4
  Top Layer w0.125: U5.9@9.16,6.875 9.923,6.875 C23.2@9.981,6.816 ; C24.2@9.988,6.24 9.988,6.823 C23.2@9.99,6.825
XC1: U1.34 X2.1 | length 3.6
  Top Layer w0.15: U1.34@5.886,1.21 6.223,1.21 7.07,2.056 8.187,2.056 8.412,2.281 8.412,2.429 X2.1@8.762,2.779
XC2: U1.35 X2.3 | length 3.6
  Top Layer w0.15: U1.35@5.825,1.6 5.835,1.61 6.198,1.61 6.917,2.328 6.917,3.479 7.262,3.824 7.262,3.879 X2.3@7.612,4.229
pads on no net: D1.3 Fid1.0 Fid2.0 Fid3.0 P1.7 P1.8 U4.2 U4.3 U4.9 U4.10 U4.11 U5.6 U5.8

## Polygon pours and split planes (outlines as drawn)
GND on Mid-Layer 2 "Mid_Layer_2-GND" (solid, remove dead copper, pour order 9): -42.935,-24.525 -42.935,21.195 40.885,21.195 40.885,-24.525
GND on Mid-Layer 1 "Mid_Layer_1-GND" (solid, remove dead copper, pour order 7): -41.629,-23.87 -41.629,21.85 41.379,21.85 41.379,-23.87
GND on Bottom Layer "Bottom_Layer-GND" (solid, remove dead copper, pour order 6): -44.41,-23.325 -44.41,22.395 39.41,22.395 39.41,-23.325
GND on Top Layer "Top_Layer-GND" (solid, remove dead copper, pour order 8): -48.485,-22.5 -48.485,23.22 35.335,23.22 35.335,-22.5

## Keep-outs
Mid-Layer 1:
  circle w0.254: c-4.95,-8.95 r0.619
  lines w0.7: 7.25,-12.557 ccw(c0,0) 7.25,12.557 ; 11.101,-0.001 12.9,0

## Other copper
Top Layer:
  region net GND: 8.212,-2.425 8.212,-1.625 7.737,-1.625 7.737,-2.425
  region net P2.06: 8.888,-2.425 8.888,-1.625 8.413,-1.625 8.413,-2.425
  region net NetQ2_3: 8.888,-3.325 8.888,-2.725 7.737,-2.725 7.737,-3.325
  rectangle net NetBz1_2: 3.675,5.1 4.275,6.05
  rectangle net P1.13: 4.575,5 5.375,5.475
  rectangle net GND: 4.575,5.675 5.375,6.15
  region net GND: 9.07,9.209 1.942,12.841 1.711,12.387 8.839,8.755
  region net GND: 2.695,15.442 1.257,12.619 1.711,12.387 3.149,15.21
  region net GND: 3.149,-15.21 1.711,-12.387 1.257,-12.618 2.695,-15.442
  region net GND: 8.839,-8.755 1.711,-12.387 1.942,-12.841 9.07,-9.209
  region net J1: 14.579,1.446 14.586,1.44 cw(c14.366,1.176) 14.708,1.207 14.458,1.179 14.43,1.429
  region net J1: 14.281,1.413 14.275,1.406 ccw(c14.544,1.182) 14.195,1.151 14.458,1.179 14.43,1.429
  region net ANT1: 14.248,1.711 14.241,1.717 cw(c14.455,1.994) 14.108,1.949 14.37,1.978 14.397,1.728
  region net ANT1: 14.547,1.744 14.552,1.751 ccw(c14.28,1.961) 14.621,2.005 14.37,1.978 14.397,1.728
  region net J1: 14.228,0.637 14.228,0.551 ccw(c14.451,0.551) 14.293,0.393 ccw(c14.338,0.437) 14.338,0.375 14.625,0.375 14.651,0.401 ccw(c14.425,0.626) 14.744,0.626 ccw(c14.717,0.599) 14.717,0.637
  region net J2: 14.228,-0.637 14.228,-0.551 cw(c14.451,-0.551) 14.293,-0.393 cw(c14.338,-0.437) 14.338,-0.375 14.625,-0.375 14.651,-0.401 cw(c14.425,-0.626) 14.744,-0.626 cw(c14.717,-0.599) 14.717,-0.637
  pour cut-out: 7.454,-12.911 cw(c7.25,-12.557) 7.046,-12.203 ccw(c0,0) 14.091,0 ccw(c0,0) 7.046,12.203 cw(c7.25,12.557) 7.454,12.911 cw(c0,0) 14.909,0 cw(c0,0)
  region net ANT2: 14.547,-1.744 14.552,-1.751 cw(c14.28,-1.961) 14.621,-2.005 14.37,-1.978 14.397,-1.728
  region net ANT2: 14.248,-1.711 14.241,-1.717 ccw(c14.455,-1.994) 14.108,-1.949 14.37,-1.978 14.397,-1.728
  region net J2: 14.281,-1.413 14.275,-1.406 cw(c14.544,-1.182) 14.195,-1.151 14.458,-1.179 14.43,-1.429
  region net J2: 14.579,-1.446 14.586,-1.44 ccw(c14.366,-1.176) 14.708,-1.207 14.458,-1.179 14.43,-1.429
  region net RF: 9.876,0.149 9.883,0.155 cw(c10.128,-0.09) 10.128,0.257 10.128,-0.001 9.876,-0.001
  region net RF: 9.876,-0.151 9.883,-0.157 ccw(c10.128,0.088) 10.128,-0.259 10.128,-0.001 9.876,-0.001
  region net RF: 11.65,0.15 11.644,0.156 ccw(c11.398,-0.089) 11.398,0.258 11.398,0 11.65,0
  region net RF: 11.65,-0.15 11.644,-0.156 cw(c11.398,0.089) 11.398,-0.258 11.398,0 11.65,0
  region net RFC: 11.95,-0.15 11.956,-0.156 ccw(c12.202,0.089) 12.202,-0.258 12.202,0 11.95,0
  region net RFC: 11.95,0.15 11.956,0.156 cw(c12.202,-0.089) 12.202,0.258 12.202,0 11.95,0
  region net RFC: 12.601,-0.258 12.629,-0.258 ccw(c12.629,-0.002) 12.81,-0.183 cw(c12.95,-0.323) 12.95,-0.125 13.026,-0.125 13.026,0 12.601,0
  region net RFC: 12.601,0.258 12.629,0.258 cw(c12.629,0.002) 12.81,0.183 ccw(c12.95,0.323) 12.95,0.125 13.026,0.125 13.026,0 12.601,0
  region net GND: 10.613,-12.238 10.713,-12.213 10.425,-11.675 10.341,-11.704 10.25,-11.795 10.25,-12.1 10.275,-12.1 10.425,-12.25
  region net GND: 10.613,12.238 10.713,12.213 10.425,11.675 10.341,11.704 10.25,11.795 10.25,12.1 10.275,12.1 10.425,12.25
  pour cut-out: 3.2,-5.1 6.6,-5.1 6.6,-8.5 3.2,-8.5
  pour cut-out: 9.506,5.002 9.506,1.747 6.638,1.747 6.638,5.002
  pour cut-out: 8.126,-0.303 8.126,-0.811 8.558,-1.243 9.244,-1.243 9.65,-0.837 9.65,-0.836 9.65,-0.303 9.8,-0.303 9.8,-0.923 9.318,-1.406 8.479,-1.406 7.971,-0.898 7.971,-0.303
  pour cut-out: 7.005,1.07 7.005,0.861 7.118,0.861 7.118,1.07
  region net NetL2_1: 6.548,0.149 6.159,0.099 6.159,-0.1 6.548,-0.151
  pour cut-out: -2.488,2.28 -2.488,1.87 -2.375,1.87 -2.375,2.28
  pour cut-out: 1.053,5.562 0.843,5.562 0.843,5.449 1.053,5.449
  pour cut-out: 3.285,3.885 2.472,3.885 2.472,5.231 3.285,5.231
  pour cut-out: -5.2,3.275 -3.8,3.275 -3.8,4.275 -5.2,4.275
  pour cut-out: 8.8,5.925 8.8,7.325 7.8,7.325 7.8,5.925
Mid-Layer 1:
  pour cut-out: 7.971,-0.407 7.971,-0.898 8.479,-1.406 9.318,-1.406 9.8,-0.923 9.8,-0.407
  pour cut-out: 6.968,0.761 6.968,-0.407 9.305,-0.407 9.686,-0.788 11.3,-0.788 11.3,0.786 9.991,0.786 9.61,0.405 7.603,0.405 7.603,0.761
Mid-Layer 2:
  pour cut-out: 6.968,0.761 6.968,-0.407 9.305,-0.407 9.686,-0.788 11.3,-0.788 11.3,0.786 9.991,0.786 9.61,0.405 7.603,0.405 7.603,0.761
  pour cut-out: 7.971,-0.407 7.971,-0.898 8.479,-1.406 9.318,-1.406 9.8,-0.923 9.8,-0.407

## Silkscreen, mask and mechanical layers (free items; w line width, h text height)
Top Overlay:
  text "ANT1" at 9.404,10.485 h1.5 r153
  text ".PCBRevision" at 14.658,7.217 h1.52 r128
  text "BTN1" at -1.6,-2.35 h1.5 r90
  text "RST" at 11.85,-6.7 h1.5 r90
  text ".PCBNumber" at 11.101,-11.93 h2.03 r52
  text "ANT2" at 6.286,-12.074 h1.5 r27
  text "BTN2" at -1.75,-12.85 h1.5
  text "GND" at -9.201,-13.466 h1.4 r330
  text "VDD" at -6.66,-13.466 h1.4 r330
  text "VBAT" at -4.12,-13.466 h1.4 r330
Bottom Overlay:
  text "nRF54L15 / TAG" at 12.667,-11.435 h2.3 r33
Board Outline:
  the board outline again, w0.1
PCB Info:
  lines w0.1: -16.5,-15.8 -16.5,-16.5 -15.8,-16.5
Bottom Assembly:
  circle w0.1: c-9.25,12 r0.5
  circle w0.1: c-9.25,12 r0.75
  circle w0.1: c-9.25,10 r0.5
  circle w0.1: c-9.25,10 r0.75
  circle w0.1: c-11.25,7 r0.5
  circle w0.1: c-11.25,7 r0.75
  circle w0.1: c-9.25,8 r0.5
  circle w0.1: c-9.25,8 r0.75
  circle w0.1: c-9.25,6 r0.5
  circle w0.1: c-9.25,6 r0.75
  circle w0.1: c-9.25,4 r0.5
  circle w0.1: c-9.25,4 r0.75
  circle w0.1: c-9.25,2 r0.5
  circle w0.1: c-9.25,2 r0.75
  circle w0.1: c-9.25,0 r0.5
  circle w0.1: c-9.25,0 r0.75
  circle w0.1: c-9.25,-2 r0.5
  circle w0.1: c-9.25,-2 r0.75
  circle w0.1: c-9.25,-4 r0.5
  circle w0.1: c-9.25,-4 r0.75
  circle w0.1: c-9.25,-6 r0.5
  circle w0.1: c-9.25,-6 r0.75
  circle w0.1: c-11.25,-7 r0.5
  circle w0.1: c-11.25,-7 r0.75
  circle w0.1: c-9.25,-8 r0.5
  circle w0.1: c-9.25,-8 r0.75
  circle w0.1: c-9.25,-10 r0.75
  circle w0.1: c-9.25,-10 r0.5
Top Impedance:
  lines w0.517: 9.34,-11.091 ccw(c0,0) 11.102,-9.327 ; 9.34,11.091 cw(c0,0) 11.102,9.327 ; 10.138,0 11.39,0 ; 11.729,-8.525 ccw(c0,0) 14.364,-1.985 ; 11.729,8.525 cw(c0,0) 14.364,1.985 ; 12.21,0 12.6,0 ; 14.453,-1.171 ccw(c0,0) 14.486,-0.634 ; 14.453,1.171 cw(c0,0) 14.486,0.634
  text "50 ohm impedance, CPW" at 9.025,-7.45 h1.78 r90
Top Via Capping:
  lines w0.15: -3.7,-13.2 -3.7,-6.2 4.3,-6.2 4.3,-13.2 -3.7,-13.2 ; -3.7,-5.716 -3.7,7.284 11.3,7.284 11.3,-5.716 -3.7,-5.716
Route Tool Path:
  lines w1: -16.934,-1.501 cw(c0,0) -16.934,1.501 ; -16.934,-1.5 -13.8,-1.5 -13.8,-2.4 -16.83,-2.4 ; -16.934,1.5 -13.8,1.5 -13.8,2.4 -16.83,2.4 cw(c0,0) -14.722,8.5 ; -16.83,-2.396 ccw(c0,0) -14.722,-8.5 ; -12.021,-12.021 ccw(c0,0) 12.021,-12.021 ; -12.021,12.021 cw(c0,0) 12.021,12.021 ; 14.722,-8.5 ccw(c0,0) 14.722,8.5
